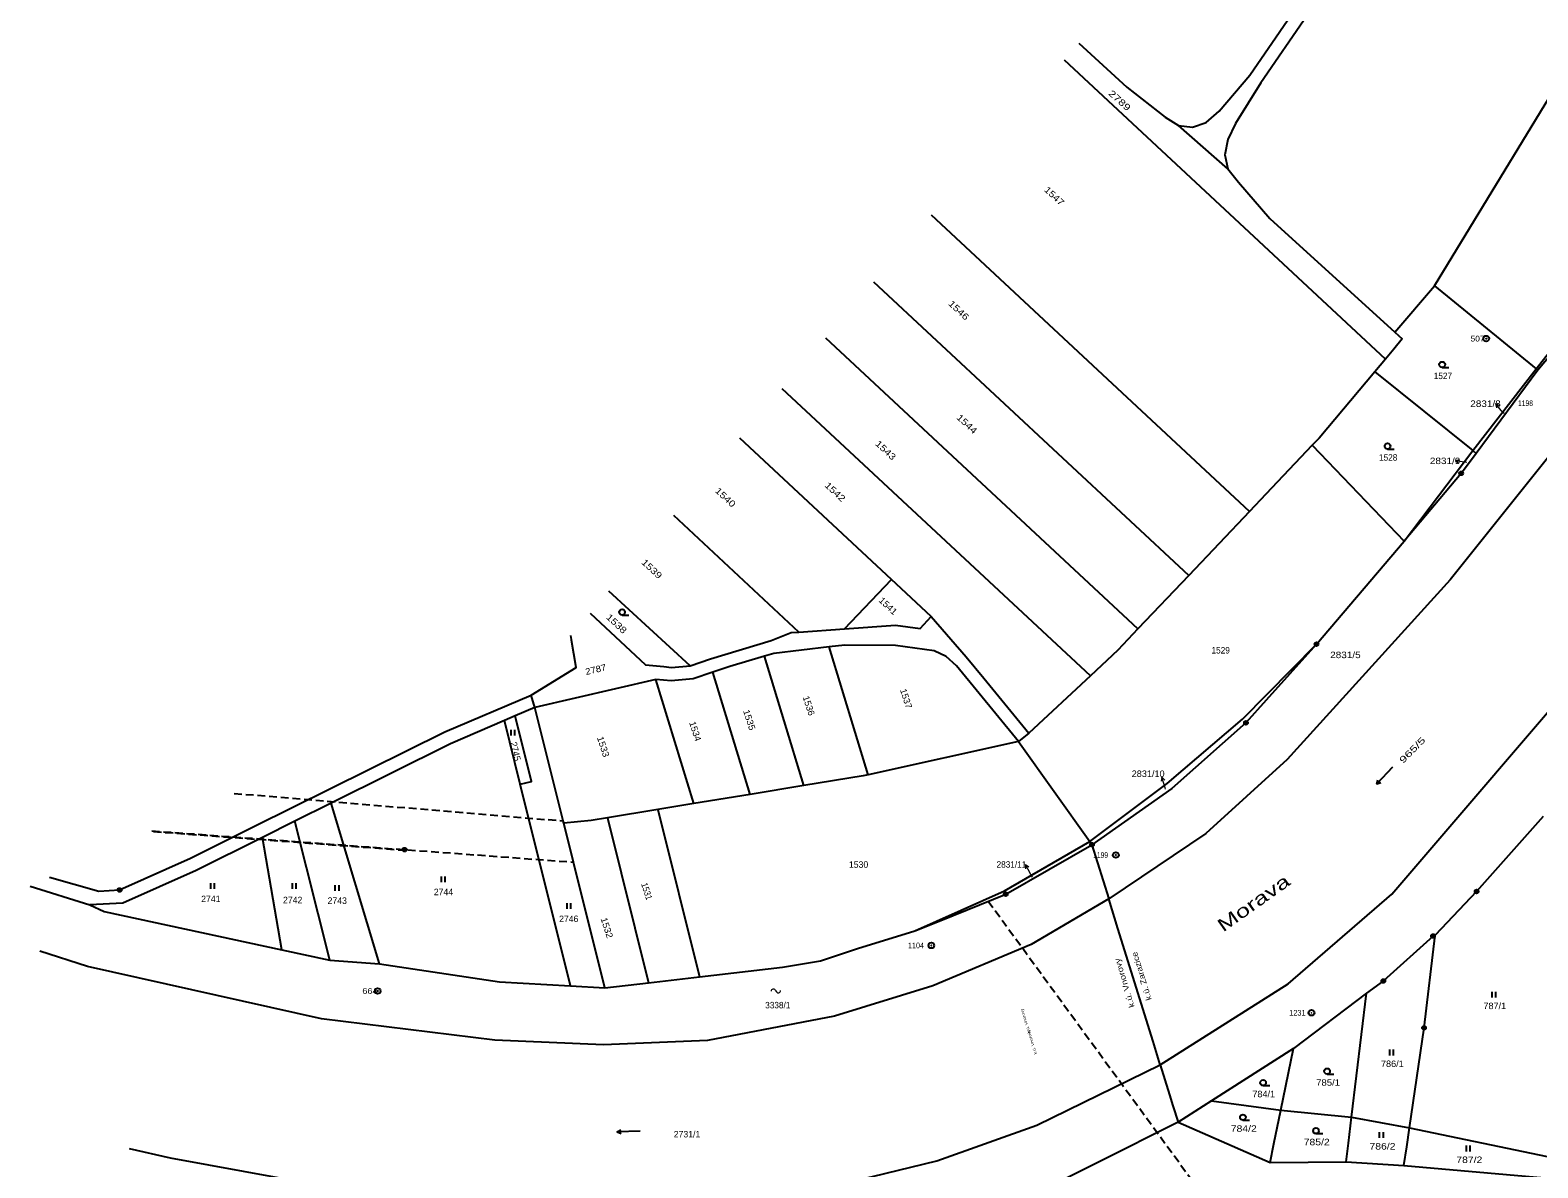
# Model space of a CAD drawing. Extents: x -546984 to -546090, y -1194931 to -1194069.
# Drawn here: x -546983.6 to -546588.4, y -1194768.4 to -1194470 of the extents above; entities that cross this region are included whole.
import ezdxf
from ezdxf.enums import TextEntityAlignment as Align

# ---------------------------------------------------------------- set-up
doc = ezdxf.new("R2010")
doc.units = 0
doc.header["$LTSCALE"] = 0.68
doc.linetypes.add('MEDIUM_DASHED', pattern=[4.5, 3, -1.5])
for name, color, linetype, lineweight in [('1', 7, 'Continuous', 25), ('3', 7, 'Continuous', 25), ('5', 7, 'Continuous', 25), ('6', 7, 'Continuous', 25), ('7', 7, 'Continuous', 13), ('8', 7, 'Continuous', 25)]:
    doc.layers.add(name, color=color, linetype=linetype, lineweight=lineweight)
doc.layers.add('2', color=7, linetype='Continuous')
doc.layers.add('37', color=7, linetype='Continuous')

msp = doc.modelspace()

# ---------------------------------------------------------------- linework, layer by layer
at = {"layer": '1'}
for p, q in [((-546628.35, -1194556.3), (-546712.507, -1194477.9)), ((-546669.67, -1194506.42), (-546682.64, -1194495)), ((-546663.99, -1194596.21), (-546747.369, -1194518.538)), ((-546679.91, -1194613.01), (-546762.45, -1194536.117)), ((-546615.48, -1194537.09), (-546588.84, -1194558.81)), ((-546693.23, -1194627.05), (-546775.065, -1194550.822)), ((-546628.35, -1194556.3), (-546631.1, -1194559.64)), ((-546588.42, -1194559.15), (-546604.55, -1194581)), ((-546588.84, -1194558.81), (-546588.42, -1194559.15)), ((-546705.72, -1194639.34), (-546786.47, -1194564.117)), ((-546647.53, -1194578.86), (-546623.43, -1194604.07)), ((-546623.43, -1194604.07), (-546605.43, -1194580.29)), ((-546605.43, -1194580.29), (-546604.55, -1194581)), ((-546810.6, -1194636.7), (-546831.971, -1194617.157)), ((-546780.82, -1194668.1), (-546791.15, -1194634.22)), ((-546764, -1194665.27), (-546774.21, -1194631.78)), ((-546794.93, -1194670.42), (-546804.69, -1194638.4)), ((-546819.59, -1194640.26), (-546851.33, -1194647.62)), ((-546809.65, -1194672.84), (-546819.59, -1194640.26)), ((-546851.33, -1194647.62), (-546852.32, -1194644.39)), ((-546856.46, -1194649.84), (-546859.32, -1194651.08)), ((-546855.17, -1194667.78), (-546859.32, -1194651.08)), ((-546724.53, -1194656.58), (-546764, -1194665.27)), ((-546724.53, -1194656.58), (-546705.88, -1194682.79)), ((-546842.01, -1194720.64), (-546855.17, -1194667.78)), ((-546904.73, -1194672.74), (-546914.28, -1194677.49)), ((-546892.1, -1194714.88), (-546904.73, -1194672.74)), ((-546917.66, -1194711.18), (-546922.74, -1194681.69)), ((-546705.88, -1194682.79), (-546705.29, -1194683.62)), ((-546705.29, -1194683.62), (-546700.89, -1194697.8)), ((-546983.646, -1194694.447), (-546968.04, -1194699.41)), ((-546821.53, -1194719.81), (-546808.14, -1194718.27)), ((-546821.53, -1194719.81), (-546808.14, -1194718.27)), ((-546833.03, -1194721.14), (-546821.53, -1194719.81)), ((-546833.03, -1194721.14), (-546821.53, -1194719.81)), ((-546687.4, -1194741.31), (-546653.83, -1194720.11)), ((-546633.3, -1194722.51), (-546652.47, -1194737.04)), ((-546687.4, -1194741.31), (-546684.95, -1194749.21)), ((-546687.4, -1194741.31), (-546684.95, -1194749.21)), ((-546682.73, -1194756.38), (-546728.98, -1194779.57)), ((-546682.73, -1194756.38), (-546658.62, -1194766.93)), ((-546658.62, -1194766.93), (-546638.65, -1194766.81)), ((-546638.65, -1194766.81), (-546623.54, -1194767.75)), ((-546623.54, -1194767.75), (-546586.67, -1194770.93))]:
    msp.add_line(p, q, dxfattribs=at)
for points in [[(-546389.24, -1194211.62), (-546383.21, -1194213.85), (-546381.43, -1194214.52), (-546374.55, -1194220.96), (-546389.16, -1194255.29), (-546392.45, -1194260.52), (-546401.16, -1194281.84), (-546427.1, -1194334), (-546466.91, -1194406.62), (-546525.73, -1194500.91), (-546575.37, -1194569.17), (-546611.42, -1194614.13), (-546654.08, -1194661.28), (-546675.45, -1194680.69), (-546700.89, -1194697.8)], [(-546653.83, -1194720.11), (-546626.66, -1194696.55), (-546572.27, -1194633.02), (-546541.58, -1194595.62), (-546489.43, -1194522.46), (-546452.3, -1194465.52), (-546414.56, -1194402.38), (-546384.23, -1194347.08), (-546351.57, -1194280.62), (-546352.84, -1194277.72), (-546335.99, -1194236.72), (-546326.04, -1194236.79), (-546324.23, -1194237.51), (-546321.88, -1194231.5)], [(-546537.08, -1194396.04), (-546541.3, -1194394.88), (-546553.58, -1194392.51), (-546556.28, -1194392.22), (-546558.81, -1194392.34), (-546563.23, -1194393.24), (-546567.48, -1194394.73), (-546573.16, -1194396.9), (-546579.06, -1194399.39), (-546603.46, -1194411.51), (-546612, -1194416.87), (-546621.27, -1194425.7), (-546648.92, -1194466.22), (-546661.06, -1194483.86), (-546667.68, -1194494.55), (-546669.7, -1194498.74), (-546670.46, -1194502.75), (-546669.67, -1194506.42)], [(-546669.67, -1194506.42), (-546666.91, -1194509.86), (-546658.64, -1194519.43), (-546625.89, -1194549.19), (-546615.48, -1194537.09), (-546575.06, -1194470.63), (-546537.08, -1194396.04)], [(-546682.64, -1194495), (-546678.92, -1194495.49), (-546675.34, -1194494.23), (-546671.96, -1194491.28), (-546663.92, -1194481.84), (-546648.2, -1194458.87)], [(-546708.693, -1194473.453), (-546696.12, -1194485.01), (-546686.1, -1194492.86), (-546682.64, -1194495)], [(-546588.84, -1194558.81), (-546573.83, -1194539.73), (-546538.72, -1194492.93)], [(-546538.72, -1194492.93), (-546572.79, -1194540.57), (-546588.42, -1194559.15)], [(-546625.89, -1194549.19), (-546623.93, -1194550.97), (-546626.19, -1194553.66), (-546628.35, -1194556.3)], [(-546631.1, -1194559.64), (-546645.76, -1194576.99), (-546647.53, -1194578.86)], [(-546631.1, -1194559.64), (-546605.43, -1194580.29), (-546588.84, -1194558.81)], [(-546782.15, -1194627.86), (-546770.2, -1194627.02), (-546757.87, -1194614.06), (-546797.578, -1194577.065)], [(-546647.53, -1194578.86), (-546659.72, -1194591.71), (-546663.99, -1194596.21)], [(-546604.55, -1194581), (-546605.57, -1194582.39), (-546608.5, -1194586.26), (-546623.43, -1194604.07)], [(-546810.6, -1194636.7), (-546805.27, -1194634.91), (-546789.41, -1194630.06), (-546784.13, -1194628), (-546782.15, -1194627.86), (-546814.946, -1194597.311)], [(-546663.99, -1194596.21), (-546679.91, -1194613.01), (-546693.23, -1194627.05)], [(-546705.88, -1194682.79), (-546685.61, -1194667.59), (-546665.8, -1194650.66), (-546646.44, -1194631.03), (-546623.43, -1194604.07)], [(-546770.2, -1194627.02), (-546756.83, -1194626.08), (-546750.37, -1194626.96), (-546747.47, -1194623.75), (-546757.87, -1194614.06)], [(-546836.88, -1194622.878), (-546822.35, -1194636.42), (-546817.57, -1194636.89), (-546815.53, -1194637.13), (-546810.6, -1194636.7)], [(-546747.47, -1194623.75), (-546738.28, -1194634.32), (-546733.63, -1194639.98), (-546721.82, -1194654.36)], [(-546693.23, -1194627.05), (-546698.47, -1194632.57), (-546705.72, -1194639.34), (-546721.82, -1194654.36), (-546724.53, -1194656.58)], [(-546852.32, -1194644.39), (-546840.55, -1194637.14), (-546841.894, -1194628.724)], [(-546852.32, -1194644.39), (-546840.55, -1194637.14), (-546841.689, -1194630.008)], [(-546724.53, -1194656.58), (-546740.83, -1194636.73), (-546743.52, -1194634.25), (-546746.68, -1194632.77), (-546756.81, -1194631.4), (-546770.11, -1194631.3), (-546774.21, -1194631.78)], [(-546646.44, -1194631.03), (-546659.61, -1194645.69), (-546664.93, -1194651.66), (-546684.38, -1194668.85), (-546705.29, -1194683.62), (-546700.89, -1194697.8)], [(-546791.15, -1194634.22), (-546800.26, -1194636.91), (-546804.69, -1194638.4)], [(-546774.21, -1194631.78), (-546788.7, -1194633.5), (-546791.15, -1194634.22)], [(-546804.69, -1194638.4), (-546809.88, -1194640.15), (-546815.58, -1194640.65), (-546819.59, -1194640.26)], [(-546978.598, -1194692.156), (-546965.65, -1194695.77), (-546960.19, -1194695.49), (-546941.61, -1194687.17), (-546924.81, -1194678.79), (-546874.9, -1194654), (-546852.32, -1194644.39)], [(-546843.77, -1194677.99), (-546843.92, -1194677.38), (-546851.33, -1194647.62), (-546852.32, -1194644.39)], [(-546859.32, -1194651.08), (-546873.43, -1194657.18), (-546904.73, -1194672.74)], [(-546843.77, -1194677.99), (-546843.92, -1194677.38), (-546851.33, -1194647.62), (-546856.46, -1194649.84)], [(-546855.17, -1194667.78), (-546852.25, -1194667.05), (-546856.46, -1194649.84)], [(-546764, -1194665.27), (-546765.31, -1194665.56), (-546780.82, -1194668.1), (-546794.93, -1194670.42), (-546809.65, -1194672.84)], [(-546819.06, -1194674.41), (-546832.3, -1194676.56), (-546821.53, -1194719.81)], [(-546809.65, -1194672.84), (-546819.06, -1194674.41), (-546808.14, -1194718.27)], [(-546905.05, -1194713.89), (-546914.28, -1194677.49), (-546922.74, -1194681.69)], [(-546832.3, -1194676.56), (-546836.61, -1194677.27), (-546843.77, -1194677.99)], [(-546833.03, -1194721.14), (-546841.23, -1194688.18), (-546843.77, -1194677.99)], [(-546833.03, -1194721.14), (-546841.23, -1194688.18), (-546843.77, -1194677.99)], [(-546587.01, -1194676.23), (-546604.46, -1194695.9), (-546615.35, -1194707.32)], [(-546922.74, -1194681.69), (-546940.12, -1194690.34), (-546959.39, -1194698.97), (-546968.04, -1194699.41)], [(-546751.76, -1194706.22), (-546728.23, -1194695.71), (-546705.88, -1194682.79)], [(-546751.76, -1194706.22), (-546744.94, -1194703.51), (-546727.91, -1194696.57), (-546705.29, -1194683.62)], [(-546751.76, -1194706.22), (-546744.94, -1194703.51), (-546727.91, -1194696.57), (-546705.29, -1194683.62)], [(-546687.4, -1194741.31), (-546689.28, -1194735.26), (-546698.47, -1194705.6), (-546700.89, -1194697.8), (-546721.21, -1194709.8)], [(-546687.4, -1194741.31), (-546689.28, -1194735.26), (-546698.47, -1194705.6), (-546700.89, -1194697.8)], [(-546968.04, -1194699.41), (-546964.25, -1194701.14), (-546917.66, -1194711.18), (-546905.05, -1194713.89), (-546892.1, -1194714.88)], [(-546808.14, -1194718.27), (-546786.38, -1194715.77), (-546776.43, -1194714.05), (-546766.78, -1194710.83), (-546751.76, -1194706.22)], [(-546808.14, -1194718.27), (-546786.38, -1194715.77), (-546776.43, -1194714.05), (-546766.78, -1194710.83), (-546751.76, -1194706.22)], [(-546721.21, -1194709.8), (-546747.03, -1194720.61), (-546772.8, -1194728.54), (-546806.1, -1194734.93), (-546833.3, -1194736.12), (-546861.83, -1194734.87), (-546907.23, -1194729.3), (-546968.6, -1194715.57), (-546981.148, -1194711.521)], [(-546615.35, -1194707.32), (-546615.87, -1194707.56), (-546628.9, -1194719.35), (-546633.3, -1194722.51)], [(-546622.04, -1194757.86), (-546618.24, -1194731.65), (-546615.35, -1194707.32)], [(-546892.1, -1194714.88), (-546860.57, -1194719.59), (-546842.01, -1194720.64), (-546833.03, -1194721.14)], [(-546658.62, -1194766.93), (-546657.62, -1194762.03), (-546655.8, -1194753.22), (-546637.23, -1194755.1), (-546633.3, -1194722.51)], [(-546652.47, -1194737.04), (-546673.97, -1194750.78), (-546682.73, -1194756.38)], [(-546673.97, -1194750.78), (-546655.8, -1194753.22), (-546652.47, -1194737.04)], [(-546832.61, -1194792.18), (-546832.81, -1194779.81), (-546791.87, -1194777.31), (-546762.86, -1194770.59), (-546745.98, -1194766.47), (-546719.75, -1194757.14), (-546687.4, -1194741.31)], [(-546684.95, -1194749.21), (-546684.05, -1194752.12), (-546682.73, -1194756.38)], [(-546684.95, -1194749.21), (-546684.05, -1194752.12), (-546682.73, -1194756.38)], [(-546682.73, -1194756.38), (-546658.62, -1194766.93), (-546638.65, -1194766.81), (-546623.54, -1194767.75), (-546586.67, -1194770.93), (-546567.2, -1194774.9)], [(-546638.65, -1194766.81), (-546638.05, -1194761.85), (-546637.23, -1194755.1), (-546622.04, -1194757.86)], [(-546623.54, -1194767.75), (-546622.76, -1194762.81), (-546622.04, -1194757.86), (-546585.99, -1194765.36)], [(-546957.649, -1194763.287), (-546946.96, -1194765.76), (-546917.78, -1194771.08), (-546918.16, -1194778.78)]]:
    msp.add_lwpolyline(points, dxfattribs=at)
at = {"layer": '3'}
for p, q in [((-546613.493, -1194558.49), (-546611.743, -1194558.49)), ((-546627.783, -1194579.87), (-546626.033, -1194579.87)), ((-546828.463, -1194623.39), (-546826.713, -1194623.39)), ((-546857.591, -1194654.97), (-546857.591, -1194653.47)), ((-546856.59, -1194654.97), (-546856.59, -1194653.47)), ((-546630.631, -1194667.661), (-546630.332, -1194666.604)), ((-546936.311, -1194695.19), (-546936.311, -1194693.69)), ((-546935.31, -1194695.19), (-546935.31, -1194693.69)), ((-546914.891, -1194695.19), (-546914.891, -1194693.69)), ((-546913.89, -1194695.19), (-546913.89, -1194693.69)), ((-546903.651, -1194695.72), (-546903.651, -1194694.22)), ((-546902.65, -1194695.72), (-546902.65, -1194694.22)), ((-546875.811, -1194693.44), (-546875.811, -1194691.94)), ((-546874.81, -1194693.44), (-546874.81, -1194691.94)), ((-546842.881, -1194700.47), (-546842.881, -1194698.97)), ((-546841.88, -1194700.47), (-546841.88, -1194698.97)), ((-546600.411, -1194723.68), (-546600.411, -1194722.18)), ((-546599.41, -1194723.68), (-546599.41, -1194722.18)), ((-546627.231, -1194738.86), (-546627.231, -1194737.36)), ((-546626.23, -1194738.86), (-546626.23, -1194737.36)), ((-546643.663, -1194743.77), (-546641.913, -1194743.77)), ((-546660.433, -1194746.79), (-546658.683, -1194746.79)), ((-546665.723, -1194755.85), (-546663.973, -1194755.85)), ((-546829.736, -1194758.91), (-546828.777, -1194758.375)), ((-546646.563, -1194759.38), (-546644.813, -1194759.38)), ((-546629.881, -1194760.51), (-546629.881, -1194759.01)), ((-546628.88, -1194760.51), (-546628.88, -1194759.01)), ((-546607.141, -1194764.03), (-546607.141, -1194762.53)), ((-546606.14, -1194764.03), (-546606.14, -1194762.53))]:
    msp.add_line(p, q, dxfattribs=at)
for points in [[(-546626.549, -1194663.263), (-546630.631, -1194667.661), (-546629.598, -1194667.285)], [(-546823.739, -1194758.7), (-546829.736, -1194758.91), (-546828.742, -1194759.377)]]:
    msp.add_lwpolyline(points, dxfattribs=at)
for centre in [(-546613.4929, -1194557.7398), (-546627.7829, -1194579.1198), (-546828.4629, -1194622.6398), (-546643.6629, -1194743.0198), (-546660.4329, -1194746.0398), (-546665.7229, -1194755.0998), (-546646.5629, -1194758.6298)]:
    msp.add_circle(centre, 0.75, dxfattribs=at)
at = {"layer": '5', "lineweight": 13}
msp.add_line((-546788.317, -1194721.764), (-546788.017, -1194722.164), dxfattribs=at)
for centre, start, end in [((-546788.8294, -1194722.0514), 29.29136, 181.21888), ((-546787.5044, -1194721.8764), 209.29136, 1.21887)]:
    msp.add_arc(centre, 0.5876, start, end, dxfattribs=at)
at = {"layer": '6', "linetype": 'MEDIUM_DASHED'}
for p, q in [((-546930.144, -1194670.16), (-546843.92, -1194677.38)), ((-546885.15, -1194685.16), (-546952.22, -1194680.182)), ((-546951.781, -1194679.982), (-546841.23, -1194688.18)), ((-546732.48, -1194698.43), (-546652.61, -1194807.81))]:
    msp.add_line(p, q, dxfattribs=at)
at = {"layer": '6'}
for radius in [0.5, 0.4, 0.3, 0.2, 0.1]:
    msp.add_circle((-546885.4734, -1194684.8999), radius, dxfattribs=at)
at = {"layer": '7'}
for p, q in [((-546599.469, -1194567.971), (-546599.209, -1194569.06)), ((-546610.032, -1194582.972), (-546609.11, -1194583.608)), ((-546686.957, -1194665.88), (-546687.143, -1194666.984)), ((-546722.745, -1194688.805), (-546722.697, -1194689.924))]:
    msp.add_line(p, q, dxfattribs=at)
for points in [[(-546597.27, -1194570.59), (-546597.54, -1194570.27), (-546599.469, -1194567.971), (-546598.442, -1194568.416)], [(-546607.06, -1194583.39), (-546610.032, -1194582.972), (-546608.97, -1194582.616)], [(-546685.99, -1194669.04), (-546686.08, -1194668.75), (-546686.957, -1194665.88), (-546686.186, -1194666.691)], [(-546720.91, -1194692.12), (-546721.29, -1194691.43), (-546722.745, -1194688.805), (-546721.821, -1194689.438)]]:
    msp.add_lwpolyline(points, dxfattribs=at)
at = {"layer": '8'}
for centre, radius in [((-546601.93, -1194550.9198), 0.75), ((-546601.93, -1194550.9198), 0.03), ((-546608.5, -1194586.2599), 0.5), ((-546608.5, -1194586.2599), 0.0303), ((-546646.44, -1194631.0299), 0.5), ((-546646.44, -1194631.0299), 0.0303), ((-546664.93, -1194651.6599), 0.5), ((-546664.93, -1194651.6599), 0.0303), ((-546705.29, -1194683.6199), 0.5), ((-546705.29, -1194683.6199), 0.5), ((-546705.29, -1194683.6199), 0.0303), ((-546705.29, -1194683.6199), 0.0303), ((-546699.04, -1194686.3198), 0.75), ((-546699.04, -1194686.3198), 0.03), ((-546960.19, -1194695.4899), 0.5), ((-546960.19, -1194695.4899), 0.0303), ((-546727.91, -1194696.5699), 0.5), ((-546727.91, -1194696.5699), 0.0303), ((-546604.46, -1194695.8999), 0.5), ((-546604.46, -1194695.8999), 0.0303), ((-546747.4, -1194710.0398), 0.75), ((-546747.4, -1194710.0398), 0.03), ((-546615.87, -1194707.5599), 0.5), ((-546615.87, -1194707.5599), 0.0303), ((-546892.55, -1194721.9798), 0.75), ((-546892.55, -1194721.9798), 0.03), ((-546628.9, -1194719.3499), 0.5), ((-546628.9, -1194719.3499), 0.0303), ((-546647.74, -1194727.6898), 0.75), ((-546647.74, -1194727.6898), 0.03), ((-546618.24, -1194731.6499), 0.5), ((-546618.24, -1194731.6499), 0.0303)]:
    msp.add_circle(centre, radius, dxfattribs=at)

# ---------------------------------------------------------------- texts
at = {"layer": '2'}
for s, rotation, width, p in [('2789', 318, 1.35, (-546701.148, -1194486.811)), ('1547', 317, 1.2, (-546717.969, -1194512.091)), ('1546', 317, 1.25, (-546743.099, -1194541.951)), ('1544', 317, 1.25, (-546740.959, -1194571.771)), ('1543', 317, 1.25, (-546762.269, -1194578.651)), ('1540', 317, 1.25, (-546804.269, -1194591.001)), ('1542', 317, 1.25, (-546775.519, -1194589.571)), ('1539', 317, 1.25, (-546823.559, -1194609.761)), ('1541', 317, 1.1, (-546761.349, -1194619.741)), ('1538', 317, 1.25, (-546832.819, -1194624.131)), ('2787', 13, 1.1, (-546837.898, -1194639.138)), ('1537', 288, 1.05, (-546755.638, -1194643.042)), ('1536', 288, 1.05, (-546781.148, -1194644.912)), ('1534', 288, 1.05, (-546810.908, -1194651.612)), ('1535', 288, 1.1, (-546796.778, -1194648.512)), ('1533', 288, 1.1, (-546835.088, -1194655.532)), ('965/5', 45.123, 1.5, (-546623.726, -1194662.427)), ('1531', 288, 0.9, (-546823.508, -1194693.922)), ('1532', 288, 1.1, (-546834.124, -1194703.015))]:
    msp.add_text(s, height=1.7, rotation=rotation, dxfattribs=dict(at, width=width)).set_placement(p)
for s, width, p in [('1527', 0.95, (-546615.7, -1194561.54)), ('1528', 0.95, (-546630.04, -1194582.92)), ('1529', 0.95, (-546673.95, -1194633.49)), ('2831/5', 1.15, (-546642.849, -1194634.702)), ('3338/1', 0.95, (-546790.956, -1194726.534)), ('787/1', 1.05, (-546602.68, -1194726.73)), ('786/1', 1.05, (-546629.53, -1194741.91)), ('785/1', 1.1, (-546646.52, -1194746.82)), ('784/1', 1.05, (-546663.25, -1194749.84)), ('784/2', 1.2, (-546668.91, -1194758.9)), ('785/2', 1.2, (-546649.79, -1194762.43)), ('786/2', 1.2, (-546632.55, -1194763.56)), ('787/2', 1.2, (-546609.78, -1194767.08))]:
    msp.add_text(s, height=1.7, dxfattribs=dict(at, width=width)).set_placement(p)
for s, width, p in [('2831/8', 1.15, (-546598.127, -1194568.83)), ('2831/9', 1.15, (-546608.718, -1194583.82)), ('2831/10', 1.05, (-546686.247, -1194665.857)), ('2831/11', 0.95, (-546722.496, -1194689.65))]:
    msp.add_text(s, height=1.7, dxfattribs=dict(at, width=width)).set_placement(p, align=Align.RIGHT)
msp.add_text('2745', height=1.7, rotation=283, dxfattribs=at).set_placement((-546857.2105, -1194659.3358), align=Align.CENTER)
msp.add_text('1530', height=1.7, dxfattribs=at).set_placement((-546769, -1194689.67))
for s, p in [('2741', (-546936.28, -1194698.676)), ('2742', (-546914.83, -1194698.966)), ('2743', (-546903.14, -1194699.136)), ('2744', (-546875.3, -1194696.856)), ('2746', (-546842.45, -1194703.906)), ('2731/1', (-546811.4485, -1194760.373))]:
    msp.add_text(s, height=1.7, dxfattribs=at).set_placement(p, align=Align.CENTER)
at = {"layer": '37'}
for s, height, rotation, width, p in [('k.ú. Vnorovy', 1.5, 107.224, 1.2, (-546696.0654, -1194719.6701)), ('k.ú. Zarazice', 1.5, 107.224, 1.15, (-546691.5779, -1194717.8691)), ('k.ú. Vnorovy', 0.75, 107.215, 1.2, (-546722.3951, -1194729.7525)), ('k.ú. Vnorovy', 0.75, 107.215, 1.2, (-546720.6871, -1194735.2655))]:
    msp.add_text(s, height=height, rotation=rotation, dxfattribs=dict(at, width=width)).set_placement(p, align=Align.CENTER)
at = {"layer": '7', "width": 1.45}
msp.add_text('Morava', height=3.4, rotation=35.425, dxfattribs=at).set_placement((-546661.9404, -1194700.2794), align=Align.CENTER)
at = {"layer": '8'}
for s, width, p in [('507', 1.1, (-546602.361, -1194551.67)), ('1198', 0.7, (-546589.688, -1194568.59)), ('1199', 0.7, (-546701.076, -1194687.07)), ('1104', 0.75, (-546749.33, -1194710.79)), ('664', 1.2, (-546892.55, -1194722.73)), ('1231', 0.8, (-546649.303, -1194728.44))]:
    msp.add_text(s, height=1.5, dxfattribs=dict(at, width=width)).set_placement(p, align=Align.RIGHT)

doc.saveas('drawing.dxf')
